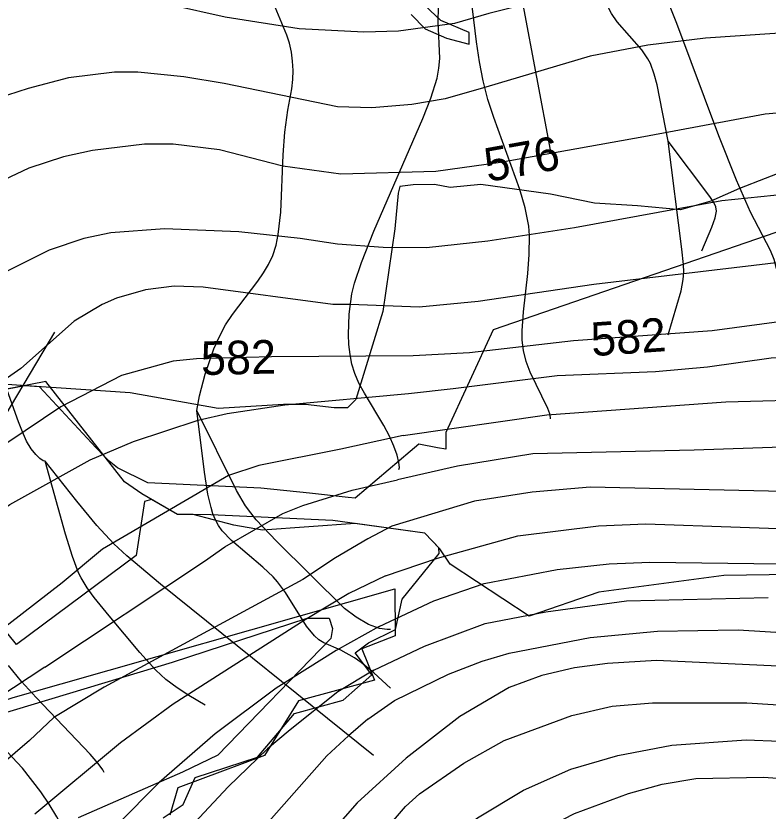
# Model space of a CAD drawing. Extents: x -709584 to -702006, y -1161789 to -1157496.
# Drawn here: x -706685.7 to -706462.3, y -1159166 to -1158929.8 of the extents above; entities that cross this region are included whole.
import ezdxf

# ---------------------------------------------------------------- set-up
doc = ezdxf.new("R2010")
doc.units = 0
for name, color, linetype in [('102_obvod PÚ', 7, 'Continuous'), ('103_hranice KÚ', 7, 'Continuous'), ('120_vrstevnice hlavní', 7, 'Continuous'), ('121_vrstevnice hlavní_popis', 7, 'Continuous'), ('122_vrstevnice základní', 7, 'Continuous'), ('408_BPEJ_linie', 7, 'Continuous'), ('411_akumulovaný odtok', 7, 'Continuous'), ('419_LPIS PB', 7, 'Continuous'), ('735_OP sítí TI', 7, 'Continuous')]:
    doc.layers.add(name, color=color, linetype=linetype)

msp = doc.modelspace()

# ---------------------------------------------------------------- linework, layer by layer
at = {"layer": '102_obvod PÚ'}
msp.add_lwpolyline([(-706805.21, -1159219.79), (-706731.4, -1159147.52), (-706686.57, -1159132.24), (-706573.17, -1159099.95), (-706573.06, -1159113.87), (-706582.98, -1159117.75), (-706579.22, -1159127.1), (-706601.81, -1159133.26), (-706611.85, -1159149.46), (-706637.63, -1159159.04), (-706640.02, -1159167.14)], dxfattribs=at)
at = {"layer": '103_hranice KÚ'}
msp.add_lwpolyline([(-706441.77, -1159095.45), (-706475.42, -1159095.96), (-706512.58, -1159100.98), (-706533.23, -1159108.06), (-706556.76, -1159092.65), (-706559.84, -1159088.08), (-706564.31, -1159083.46), (-706591.56, -1159079.67), (-706627.84, -1159077.93), (-706637.69, -1159077.84), (-706648.36, -1159071.71), (-706653.44, -1159068.18), (-706676.84, -1159038.41), (-706710.91, -1159044.97)], dxfattribs=at)
msp.add_lwpolyline([(-706441.77, -1159095.45), (-706475.42, -1159095.96), (-706512.58, -1159100.98), (-706533.23, -1159108.06), (-706556.76, -1159092.65), (-706559.84, -1159088.08), (-706564.31, -1159083.46), (-706591.56, -1159079.67), (-706627.84, -1159077.93), (-706637.69, -1159077.84), (-706648.36, -1159071.71), (-706653.44, -1159068.18), (-706676.84, -1159038.41), (-706710.91, -1159044.97)], dxfattribs=at)
at = {"layer": '120_vrstevnice hlavní'}
for points in [[(-706176.41, -1159124.39), (-706181.99, -1159121.81), (-706201.58, -1159107.37), (-706215.31, -1159095.79), (-706241.34, -1159071.76), (-706259.5, -1159056.89), (-706285.82, -1159039.44), (-706302.98, -1159030.72), (-706320.14, -1159023.56), (-706341.59, -1159016.13), (-706375.91, -1159006.83), (-706393.08, -1159003.69), (-706418.82, -1159001.54), (-706437.12, -1159001.11), (-706456.57, -1159002.69), (-706514.06, -1159009.55), (-706548.39, -1159014.55), (-706565.96, -1159016.25)], [(-706565.96, -1159016.25), (-706586.43, -1159015.44), (-706591.54, -1159015.44), (-706630.12, -1159010.3), (-706638.69, -1159010.02), (-706647.26, -1159011.16), (-706655.83, -1159013.59), (-706660.12, -1159015.44), (-706668.4, -1159020.44), (-706684.26, -1159034.45), (-706691.98, -1159039.87), (-706700.12, -1159044.59), (-706742.84, -1159067.16), (-706754.27, -1159074.3), (-706790.84, -1159102.3), (-706809.27, -1159118.45), (-706814.84, -1159122.59), (-706826.94, -1159133.8), (-706840, -1159144.91), (-706849.7, -1159152.02), (-706865.13, -1159165.88), (-706879.98, -1159182.17)], [(-706187.03, -1159242.28), (-706197.21, -1159228.05), (-706208.76, -1159215.69), (-706225.25, -1159199.21), (-706251.21, -1159173.3), (-706276.23, -1159148.27), (-706307.12, -1159120.96), (-706316.13, -1159114.52), (-706333.3, -1159103.94), (-706354.75, -1159093.36), (-706371.91, -1159086.63), (-706393.36, -1159080.05), (-706419.1, -1159074.19), (-706427.68, -1159073.05), (-706457.72, -1159071.05), (-706515.21, -1159069.76), (-706532.37, -1159071.19), (-706549.53, -1159073.91), (-706574.08, -1159081.34)], [(-706574.08, -1159081.34), (-706581.23, -1159085.07), (-706590.76, -1159090.76), (-706600.54, -1159097.16)], [(-706600.54, -1159097.16), (-706659.52, -1159129.18), (-706674.4, -1159138.16), (-706681.69, -1159145.02), (-706715.12, -1159173.74)], [(-706446.56, -1159123.53), (-706495.47, -1159121.24), (-706510.06, -1159122.1), (-706519.79, -1159123.39), (-706529.51, -1159125.68), (-706539.23, -1159129.25), (-706553.82, -1159137.83), (-706569.84, -1159150.28), (-706584.33, -1159163.53)], [(-706584.33, -1159163.53), (-706594.38, -1159174.88)]]:
    msp.add_lwpolyline(points, dxfattribs=at)
for points in [[(-706565.96, -1159016.25), (-706565.96, -1159016.25)], [(-706574.08, -1159081.34), (-706574.08, -1159081.34)], [(-706584.33, -1159163.53), (-706584.33, -1159163.53)]]:
    msp.add_open_spline(points, degree=1, dxfattribs=at)
at = {"layer": '122_vrstevnice základní'}
for points in [[(-706404.99, -1158911.65), (-706434.86, -1158912.53), (-706455.81, -1158914.15), (-706486.77, -1158916.91), (-706513.74, -1158921.24), (-706529.55, -1158925.11), (-706545.24, -1158929.03), (-706555.46, -1158932.01)], [(-706555.46, -1158932.01), (-706572.11, -1158934.3), (-706582.4, -1158934.58), (-706601.54, -1158933.58), (-706623.54, -1158930.15), (-706639.55, -1158926.58)], [(-706249.92, -1158991.25), (-706321.81, -1158953.78), (-706339.81, -1158945.39), (-706356.89, -1158939.19), (-706385.64, -1158934.47), (-706401.08, -1158933.04), (-706412.24, -1158932.75), (-706439.7, -1158933.61), (-706480.89, -1158936.33), (-706498.05, -1158938.47), (-706515.21, -1158941.76), (-706546.1, -1158950.92), (-706558.24, -1158954.36)], [(-706558.25, -1158954.36), (-706568.11, -1158956.12), (-706579.96, -1158957.11), (-706590.16, -1158956.78), (-706623.83, -1158949.87), (-706635.83, -1158947.87), (-706649.55, -1158946.44), (-706656.4, -1158946.44), (-706670.12, -1158948.16), (-706682.12, -1158951.3), (-706697.55, -1158956.3)], [(-706436.84, -1158956.64), (-706463.15, -1158958.92), (-706499.19, -1158965.65), (-706541.77, -1158973.33), (-706560.95, -1158976.03)], [(-706560.95, -1158976.03), (-706589.26, -1158976.73), (-706606.4, -1158974.44), (-706625.26, -1158969.58), (-706638.97, -1158967.87), (-706647.55, -1158967.87), (-706662.98, -1158969.73), (-706671.55, -1158971.58), (-706681.83, -1158975.01), (-706705.83, -1158986.3), (-706715.55, -1158991.73), (-706743.84, -1159009.59), (-706755.98, -1159016.73), (-706771.55, -1159025.3), (-706805.55, -1159043.45), (-706819.55, -1159052.73), (-706857.41, -1159079.88), (-706882.98, -1159100.59), (-706908.27, -1159124.45), (-706928.99, -1159148.88), (-706951.56, -1159181.45)], [(-706445.13, -1158981.52), (-706476.02, -1158984.67), (-706519.79, -1158992.68), (-706545.53, -1158996.68), (-706563.77, -1158998.62)], [(-706563.77, -1158998.62), (-706576.67, -1158998.58), (-706590.16, -1158997.59), (-706601.26, -1158995.87), (-706619.54, -1158993.87), (-706641.55, -1158993.01), (-706657.55, -1158994.16), (-706665.55, -1158995.87), (-706675.83, -1158999.3), (-706694.12, -1159008.44), (-706741.41, -1159036.02), (-706762.41, -1159045.87), (-706765.41, -1159047.87), (-706771.55, -1159050.3), (-706790.41, -1159062.16), (-706809.27, -1159075.73), (-706831.7, -1159095.73), (-706863.98, -1159122.88), (-706885.84, -1159144.88), (-706922.7, -1159185.02)], [(-706442.84, -1159018.42), (-706478.88, -1159023.28), (-706520.07, -1159026.28), (-706550.96, -1159029.86), (-706567.77, -1159030.76)], [(-706567.77, -1159030.76), (-706609.83, -1159031.02), (-706632.12, -1159031.59), (-706638.97, -1159032.3), (-706654.4, -1159036.59), (-706672.4, -1159045.87), (-706698.83, -1159063.59), (-706717.41, -1159074.73), (-706740.12, -1159089.73), (-706770.27, -1159111.59), (-706785.41, -1159124.02), (-706808.41, -1159144.88), (-706817.27, -1159154.02), (-706820.27, -1159157.88), (-706874.33, -1159216.6)], [(-706569.16, -1159041.88), (-706555.83, -1159040.44), (-706524.93, -1159036.58), (-706495.76, -1159035.44), (-706480.31, -1159034.01), (-706461.44, -1159031.29), (-706449.42, -1159030.57), (-706430.55, -1159031), (-706399.65, -1159033.29), (-706380.78, -1159036.29), (-706358.47, -1159041.87), (-706335.58, -1159049.88), (-706321.28, -1159056.6), (-706304.84, -1159065.47), (-706287.39, -1159076.62), (-706271.94, -1159088.64), (-706223.75, -1159135.97), (-706216.02, -1159142.55), (-706200.43, -1159156.33), (-706190.54, -1159163.06)], [(-706896.34, -1159305.76), (-706891.06, -1159299.33), (-706868.97, -1159246.1), (-706862.43, -1159234.32), (-706837.41, -1159204.45), (-706811.55, -1159175.45), (-706794.98, -1159159.17), (-706778.12, -1159144.59), (-706752.98, -1159125.88), (-706702.69, -1159085.59), (-706687.55, -1159074.88), (-706663.69, -1159061.59), (-706650.83, -1159056.16), (-706631.55, -1159049.87), (-706622.97, -1159047.87), (-706605.83, -1159045.3), (-706569.16, -1159041.88)], [(-706570.73, -1159054.45), (-706528.08, -1159048.31), (-706474.88, -1159044.45), (-706445.7, -1159043.59), (-706426.83, -1159044.02), (-706411.38, -1159045.16), (-706383.92, -1159049.88), (-706370.19, -1159053.03), (-706357.89, -1159057.03), (-706342.02, -1159063.32), (-706323.29, -1159072.48), (-706311.99, -1159079.77), (-706296.11, -1159092.21), (-706259.93, -1159123.96), (-706248.78, -1159134.83), (-706239.48, -1159145.84), (-706231.26, -1159153.59), (-706220.87, -1159161.68)], [(-706570.73, -1159054.45), (-706589.26, -1159058.45), (-706613.54, -1159063.3), (-706622.54, -1159066.3), (-706659.98, -1159088.16), (-706671.98, -1159098.16), (-706691.92, -1159113.47)], [(-706446.56, -1159057.46), (-706484.32, -1159058.75), (-706532.2, -1159059.89), (-706554.53, -1159063.47), (-706572.37, -1159067.6)], [(-706677.1, -1159123.23), (-706629.69, -1159091.73), (-706623.69, -1159087.45), (-706606.4, -1159077.59), (-706600.54, -1159075.16), (-706585.82, -1159070.68), (-706572.37, -1159067.6)], [(-706575.93, -1159096.13), (-706560.53, -1159090.79), (-706536.66, -1159084.2), (-706512.64, -1159081.2), (-706498.62, -1159080.63), (-706442.56, -1159082.63)], [(-706577.8, -1159111.17), (-706561.55, -1159103.51), (-706546.67, -1159098.36), (-706524.93, -1159094.21), (-706509.49, -1159092.5), (-706497.48, -1159092.07), (-706451.14, -1159092.64)], [(-706575.93, -1159096.13), (-706586.81, -1159101.29), (-706599.83, -1159109.16), (-706638.97, -1159134.16), (-706654.69, -1159145.74), (-706680.12, -1159166.88)], [(-706579.42, -1159124.09), (-706564.41, -1159116.95), (-706546.39, -1159110.23), (-706528.37, -1159106.8), (-706504.34, -1159103.51), (-706462.29, -1159102.51)], [(-706577.8, -1159111.18), (-706590.56, -1159118.27), (-706608.4, -1159129.45), (-706626.54, -1159143.02), (-706643.12, -1159157.45), (-706668.12, -1159182.59)], [(-706581.23, -1159138.66), (-706573.27, -1159133.11), (-706557.26, -1159125.25), (-706547.24, -1159121.39), (-706539.23, -1159119.1), (-706515.21, -1159114.38), (-706495.19, -1159112.52), (-706471.16, -1159112.09), (-706455.14, -1159113.09)], [(-706677.1, -1159123.23), (-706695.83, -1159135.45), (-706715.69, -1159150.17), (-706735.69, -1159167.74), (-706763.69, -1159195.45), (-706783.7, -1159217.45), (-706805.84, -1159244.6), (-706817.98, -1159263.03), (-706836.98, -1159293.6), (-706845.7, -1159304.17), (-706859.84, -1159317.89), (-706876.41, -1159330.17), (-706889.99, -1159343.75), (-706898.42, -1159355.89), (-706903.84, -1159367.03), (-706906.27, -1159374.75), (-706908.27, -1159387.61), (-706908.42, -1159392.75), (-706907.7, -1159400.61)], [(-706579.42, -1159124.09), (-706590.1, -1159130.58), (-706604.26, -1159141.88), (-706610.97, -1159147.45), (-706622.69, -1159158.74), (-706651.26, -1159189.31)], [(-706587.47, -1159188.67), (-706576.99, -1159172.87), (-706569.98, -1159164.58), (-706565.84, -1159160.86), (-706552.68, -1159151.71), (-706540.67, -1159144.98), (-706520.64, -1159137.55), (-706508.63, -1159134.83), (-706496.62, -1159133.83), (-706468.59, -1159133.83), (-706454.57, -1159134.69)], [(-706581.23, -1159138.66), (-706586.95, -1159143.6), (-706593.38, -1159149.6), (-706611.26, -1159169.88)], [(-706590.33, -1159211.58), (-706586.77, -1159205.29), (-706581.39, -1159197.71), (-706571.02, -1159186.34), (-706560.85, -1159177.37), (-706548.67, -1159168.01), (-706534.95, -1159159.72), (-706520.93, -1159153.56), (-706506.91, -1159149.42), (-706490.9, -1159146.41), (-706468.87, -1159144.84), (-706438.84, -1159145.99)], [(-706596.61, -1159261.98), (-706595.45, -1159258.73), (-706586.43, -1159230.65), (-706582.14, -1159221.5), (-706577.71, -1159214.2), (-706571.98, -1159206.48), (-706560.97, -1159194.47), (-706546.96, -1159182.6), (-706535.8, -1159174.87), (-706519.79, -1159166.72), (-706503.77, -1159160.72), (-706493.76, -1159158), (-706483.75, -1159156.28), (-706463.72, -1159155.85), (-706445.7, -1159157.14)]]:
    msp.add_lwpolyline(points, dxfattribs=at)
for points in [[(-706555.46, -1158932.01), (-706555.46, -1158932.01)], [(-706558.24, -1158954.36), (-706558.25, -1158954.36)], [(-706560.95, -1158976.03), (-706560.95, -1158976.03)], [(-706563.77, -1158998.62), (-706563.77, -1158998.62)], [(-706567.77, -1159030.76), (-706567.77, -1159030.76)], [(-706569.16, -1159041.88), (-706569.16, -1159041.88)], [(-706570.73, -1159054.45), (-706570.73, -1159054.45)], [(-706572.37, -1159067.6), (-706572.37, -1159067.6)], [(-706575.93, -1159096.13), (-706575.93, -1159096.13)], [(-706577.8, -1159111.17), (-706577.8, -1159111.18)], [(-706579.42, -1159124.09), (-706579.42, -1159124.09)], [(-706581.23, -1159138.66), (-706581.23, -1159138.66)]]:
    msp.add_open_spline(points, degree=1, dxfattribs=at)
at = {"layer": '408_BPEJ_linie'}
for points in [[(-706454, -1158992), (-706544, -1159023), (-706558, -1159053.5), (-706558, -1159058.5), (-706560.49, -1159058.03), (-706566, -1159057), (-706568.6, -1159059.19), (-706585, -1159073), (-706587.01, -1159072.78), (-706598.55, -1159071.55), (-706613, -1159070), (-706646.5, -1159068.5), (-706655.5, -1159064), (-706658, -1159062), (-706659.39, -1159060.61), (-706662, -1159058), (-706678.67, -1159039.9), (-706683.06, -1159039.61), (-706699.05, -1159042.69)], [(-706642, -1159168), (-706636, -1159164), (-706632.5, -1159156), (-706614, -1159150), (-706603, -1159137), (-706588.5, -1159133), (-706580, -1159125.5), (-706585, -1159119), (-706581, -1159116), (-706573, -1159112), (-706571, -1159103), (-706560, -1159089.5), (-706560.12, -1159087.79), (-706564.31, -1159083.46), (-706585, -1159080.58), (-706612.5, -1159082.5), (-706621, -1159081), (-706633.08, -1159077.88), (-706637.69, -1159077.84), (-706645.41, -1159073.4), (-706647.5, -1159074), (-706650, -1159090), (-706685.5, -1159116.5), (-706701, -1159097.5)]]:
    msp.add_lwpolyline(points, dxfattribs=at)
at = {"layer": '411_akumulovaný odtok'}
for points in [[(-706491.99, -1158967), (-706495.23, -1158950.28), (-706496.12, -1158947.03), (-706497.27, -1158943.95), (-706498, -1158942.49), (-706499.78, -1158939.88), (-706507.14, -1158931.51), (-706508.87, -1158929.07), (-706509.53, -1158927.8), (-706509.97, -1158926.48), (-706510.17, -1158923.76), (-706509, -1158915.29), (-706509.01, -1158913.97), (-706509.24, -1158912.72), (-706509.75, -1158911.52), (-706510.5, -1158910.4), (-706511.42, -1158909.35), (-706515.98, -1158905.06), (-706517.91, -1158902.5), (-706518.45, -1158901.23), (-706518.63, -1158900.03), (-706518.48, -1158899.08), (-706517.71, -1158897.61), (-706516.99, -1158897)], [(-706451.99, -1159054.5), (-706454.46, -1159032.22), (-706456.28, -1159019.5), (-706457.64, -1159013.17), (-706460.49, -1159002.09), (-706461.56, -1158999.42), (-706467.51, -1158988.09), (-706471.71, -1158978.59), (-706476.9, -1158965.4), (-706489.44, -1158931.98), (-706493.34, -1158922.06), (-706494.77, -1158918.75), (-706496.61, -1158915.21), (-706498.85, -1158911.57), (-706501.47, -1158907.98), (-706504.31, -1158904.67), (-706507.24, -1158901.79), (-706510.1, -1158899.5), (-706512.75, -1158897.91), (-706514.83, -1158897.11), (-706516.32, -1158896.84), (-706516.99, -1158897)], [(-706526.99, -1158969.5), (-706535.08, -1158926.33), (-706535.97, -1158922.4), (-706536.77, -1158919.95), (-706537.96, -1158917.85), (-706539.72, -1158916.34), (-706540.97, -1158915.67), (-706545.68, -1158913.88), (-706551.99, -1158912)], [(-706526.99, -1159049.5), (-706526.9, -1159049.05), (-706527.14, -1159047.99), (-706527.71, -1159046.42), (-706532.99, -1159035.6), (-706534.17, -1159032.42), (-706534.95, -1159029.18), (-706535.31, -1159026.09), (-706535.32, -1159023.28), (-706534.93, -1159017.69), (-706533.72, -1159006.32), (-706533.26, -1159000.63), (-706533.2, -1158994.99), (-706533.41, -1158992.2), (-706534.46, -1158986.75), (-706536.05, -1158981.36), (-706543.76, -1158959.97), (-706545.51, -1158954.57), (-706546.93, -1158949.06), (-706548, -1158943.43), (-706548.9, -1158937.46), (-706551.99, -1158912)], [(-706571.99, -1159064.5), (-706571.81, -1159063.89), (-706571.98, -1159062.41), (-706572.5, -1159060.23), (-706573.44, -1159057.53), (-706574.77, -1159054.6), (-706576.45, -1159051.47), (-706582.21, -1159041.83), (-706583.86, -1159038.81), (-706585.09, -1159036.02), (-706585.92, -1159033.24), (-706586.47, -1159030.36), (-706586.79, -1159027.41), (-706586.94, -1159024.42), (-706586.75, -1159018.36), (-706585.9, -1159012.33), (-706585.13, -1159009.19), (-706583.08, -1159002.97), (-706579.37, -1158993.75), (-706564.81, -1158960.27), (-706562.49, -1158954.23), (-706560.65, -1158948.25), (-706560.06, -1158945.3), (-706559.8, -1158942.38), (-706560.33, -1158931.31), (-706560.07, -1158923.31)], [(-706631.99, -1159047), (-706631.17, -1159042.57), (-706629.52, -1159036.18), (-706626.95, -1159028.68), (-706625.29, -1159024.95), (-706623.42, -1159021.51), (-706621.43, -1159018.41), (-706613.84, -1159008.56), (-706612.16, -1159006.11), (-706610.67, -1159003.57), (-706609.45, -1159000.93), (-706608.46, -1158997.87), (-706607.79, -1158994.68), (-706607.03, -1158988.05), (-706606.3, -1158971), (-706605.85, -1158964.27), (-706605, -1158957.76), (-706603.79, -1158951.4), (-706603.49, -1158948.68), (-706603.4, -1158945.95), (-706603.52, -1158943.23), (-706603.85, -1158940.54), (-706604.44, -1158937.9), (-706605.25, -1158935.49), (-706609.25, -1158925.97)], [(-706481.99, -1158999.5), (-706479.03, -1158992.54), (-706478.02, -1158989.77), (-706477.65, -1158987.75), (-706477.84, -1158986.45), (-706478.42, -1158985.2), (-706479.62, -1158983.36), (-706491.99, -1158967)], [(-706491.99, -1159024.5), (-706488.18, -1159011.38), (-706487.53, -1159008.08), (-706487.38, -1159005.84), (-706487.46, -1159003.57), (-706487.92, -1158999.01), (-706491.99, -1158967)], [(-706676.99, -1159062), (-706677.57, -1159061.91), (-706678.56, -1159061.25), (-706679.82, -1159060.05), (-706681.2, -1159058.34), (-706682.55, -1159056.06), (-706683.8, -1159053.35), (-706684.96, -1159050.34), (-706688.26, -1159040.9)], [(-706574.49, -1159112), (-706575.42, -1159112.06), (-706577.69, -1159111.72), (-706580.95, -1159110.57), (-706584.7, -1159108.39), (-706588.1, -1159105.78), (-706608.31, -1159085.81), (-706614.36, -1159079.42), (-706617.53, -1159075.25), (-706620.19, -1159070.72), (-706631.99, -1159047)], [(-706574.49, -1159129.5), (-706579.4, -1159124.86), (-706583.16, -1159121.84), (-706585.19, -1159120.43), (-706589.24, -1159118.19), (-706594.3, -1159116.01), (-706595.75, -1159115.09), (-706597.08, -1159113.93), (-706599.39, -1159111.07), (-706605.62, -1159101.05), (-706607.98, -1159097.86), (-706609.35, -1159096.35), (-706612.33, -1159093.54), (-706621.72, -1159085.59), (-706624.43, -1159082.72), (-706625.55, -1159081.14), (-706626.45, -1159079.45), (-706627.18, -1159077.64), (-706627.77, -1159075.76), (-706628.68, -1159071.84), (-706629.73, -1159065.29), (-706631.99, -1159047)], [(-706644.49, -1159229.5), (-706645.23, -1159229.01), (-706646.61, -1159227.34), (-706648.43, -1159224.65), (-706650.43, -1159221.06), (-706652.2, -1159217.17), (-706657.19, -1159203.55), (-706660.53, -1159195.29), (-706665.13, -1159185.81), (-706671.67, -1159171.26), (-706673.51, -1159167.71), (-706675.8, -1159163.91), (-706678.3, -1159160.23), (-706683.79, -1159153.24), (-706689.77, -1159146.77), (-706692.95, -1159143.8), (-706701.46, -1159136.71), (-706704.1, -1159134.2), (-706706.52, -1159131.48), (-706713.23, -1159122.55), (-706718.7, -1159115.63), (-706727.52, -1159105.45), (-706742.84, -1159088.68), (-706776.99, -1159052)], [(-706629.49, -1159134.5), (-706634.36, -1159131.63), (-706637.81, -1159129.39), (-706641.2, -1159126.88), (-706644.16, -1159124.15), (-706648.87, -1159118.87), (-706658.02, -1159107.99), (-706662.47, -1159102.48), (-706664.55, -1159099.65), (-706666.37, -1159096.68), (-706667.12, -1159095.16), (-706668.95, -1159090.37), (-706670.94, -1159083.75), (-706676.99, -1159062)], [(-706579.49, -1159149.5), (-706642.76, -1159098.56), (-706652.8, -1159090.18), (-706656.61, -1159086.63), (-706661.66, -1159081.15), (-706667.58, -1159073.95), (-706676.99, -1159062)], [(-706659.49, -1159154.5), (-706659.86, -1159153.71), (-706661.29, -1159151.81), (-706663.65, -1159149.02), (-706679.67, -1159132.27), (-706684.03, -1159127.45), (-706687.91, -1159122.75)]]:
    msp.add_lwpolyline(points, dxfattribs=at)
at = {"layer": '419_LPIS PB'}
for points in [[(-706568.37, -1158929.36), (-706564.13, -1158933.59), (-706557.78, -1158936.41), (-706551.08, -1158938.18), (-706551.08, -1158934.65), (-706559.55, -1158931.12), (-706565.9, -1158925.13)], [(-706455.53, -1158975.06), (-706470.8, -1158981.08), (-706479.31, -1158984.84), (-706488.3, -1158987.4), (-706501.1, -1158986.2), (-706513.9, -1158985.4), (-706526.9, -1158982.7), (-706547.6, -1158979.8), (-706556.72, -1158980.7), (-706561.43, -1158979.88), (-706567.69, -1158979.92), (-706571.7, -1158980.42), (-706572.2, -1158982.43), (-706573.2, -1158992.97), (-706576.7, -1159017.57), (-706584.71, -1159043.68), (-706587.21, -1159046.19), (-706591.22, -1159046.19), (-706599.73, -1159045.19), (-706606.23, -1159045.19), (-706625.6, -1159046.4), (-706651.78, -1159041.68), (-706697.33, -1159038.66)], [(-706778.87, -1159189.54), (-706740.83, -1159156.41), (-706719.81, -1159145.36), (-706690.78, -1159137.32), (-706639.22, -1159121.76), (-706599.18, -1159108.7), (-706592.67, -1159108.7), (-706591.67, -1159111.72), (-706592.17, -1159114.73), (-706625.7, -1159149.38), (-706636.22, -1159154.4), (-706667.25, -1159167.95)]]:
    msp.add_lwpolyline(points, dxfattribs=at)
at = {"layer": '735_OP sítí TI'}
msp.add_lwpolyline([(-706870.8, -1160215.44), (-706873.24, -1160121.39), (-706875.97, -1160029.91), (-706878.81, -1159867.48), (-706880.66, -1159769.89), (-706883.19, -1159670.4), (-706885.78, -1159542.05), (-706887.93, -1159422.91), (-706873.77, -1159379.35), (-706858.66, -1159333.25), (-706787.46, -1159213.45), (-706723.81, -1159107.26), (-706674.12, -1159023.69)], dxfattribs=at)

# ---------------------------------------------------------------- texts
at = {"layer": '121_vrstevnice hlavní_popis'}
for s, rotation, p in [('576', 10.1817, (-706545.59, -1158979.12)), ('582', 3.9406, (-706514.6, -1159030.86)), ('582', 1.286, (-706630.66, -1159036.47))]:
    msp.add_text(s, height=10, rotation=rotation, dxfattribs=at).set_placement(p)

doc.saveas('drawing.dxf')
